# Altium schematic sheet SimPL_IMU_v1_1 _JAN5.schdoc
size 299 x 236 mm
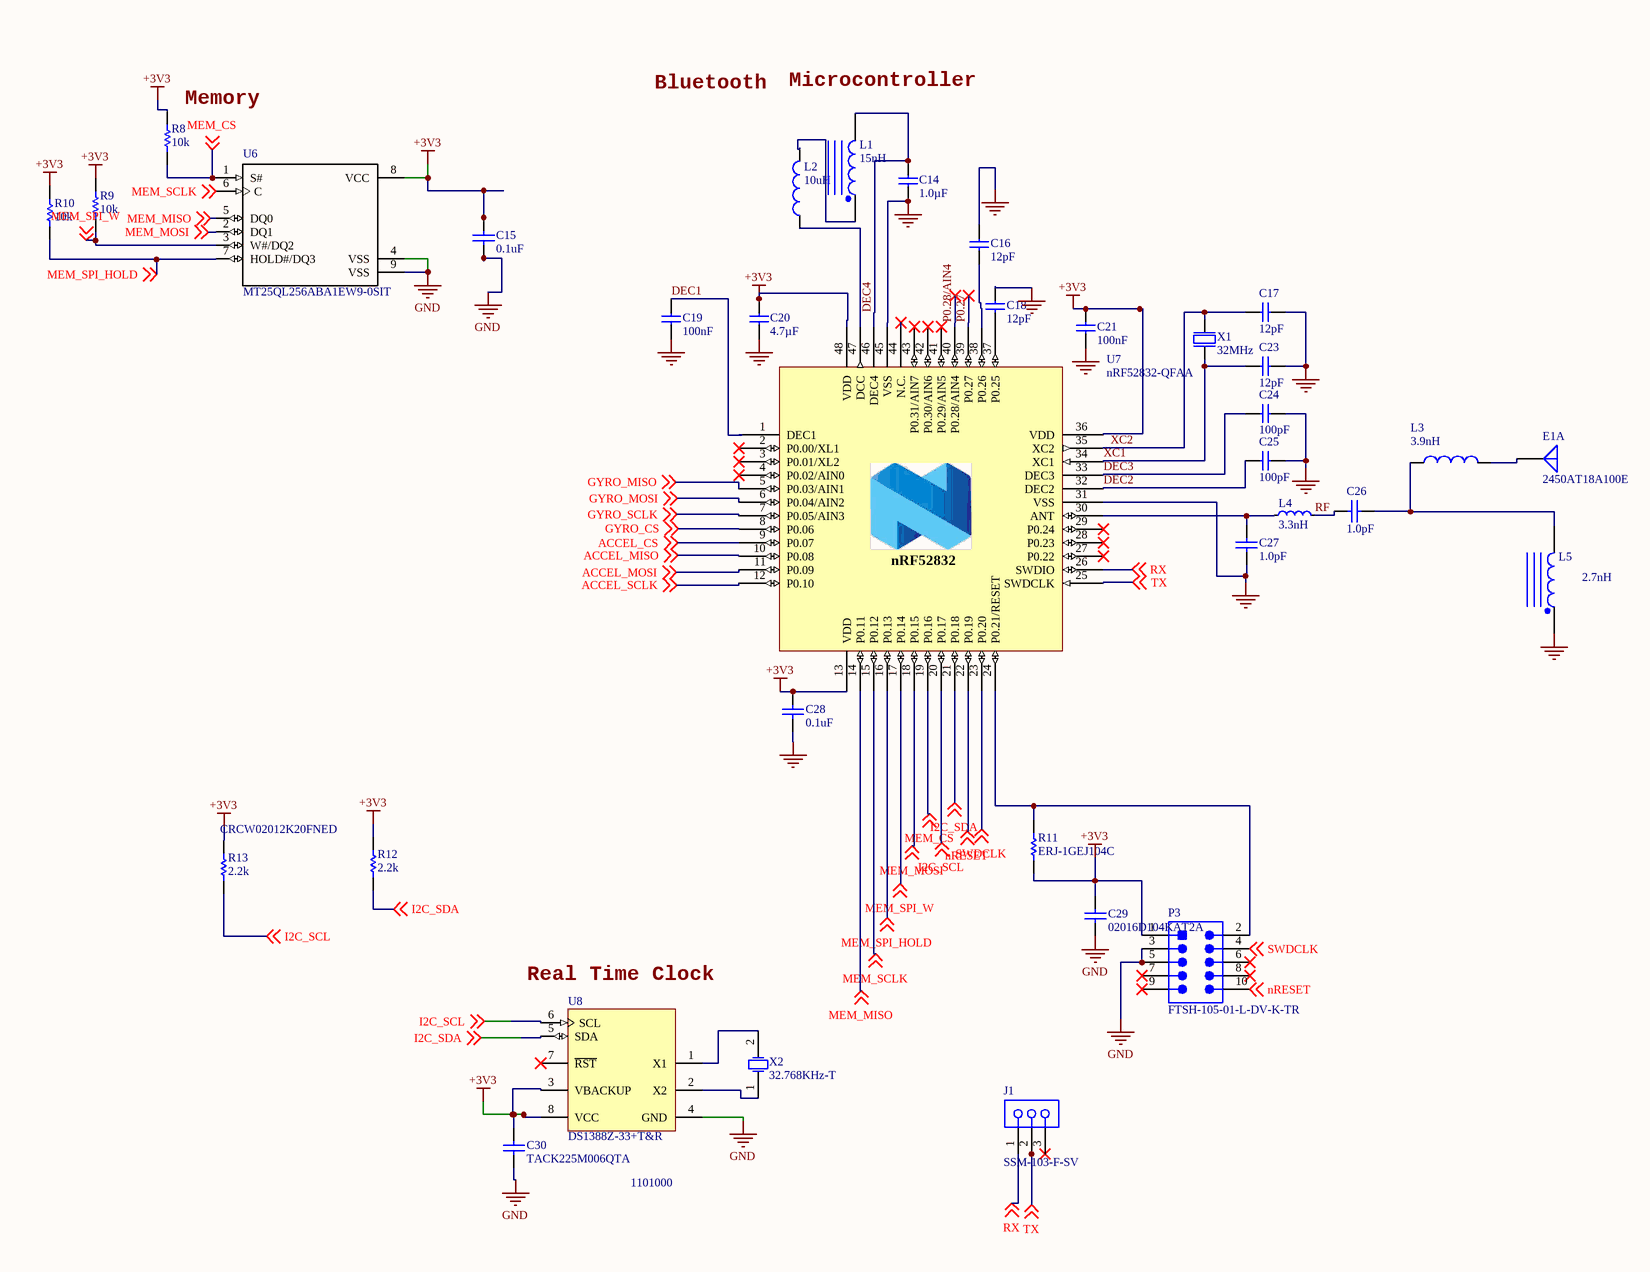
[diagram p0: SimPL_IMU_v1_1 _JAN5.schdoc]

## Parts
C14  1.0µF  [CAPC1005X04L]
C15  0.1uF  [CAPC0603X33X15LL03T05]
C16  12pF  [CAPC0603X03L]
C17  12pF  [CAPC0603X03L]
C18  12pF  [CAPC0603X03L]
C19  100nF  [CAPC0603X03L]
C20  4.7µF  [CAPC1608X06L]
C21  100nF  [CAPC0603X03L]
C23  12pF  [CAPC0603X03L]
C24  100pF  [CAPC0603X03L]
C25  100pF  [CAPC0603X03L]
C26  1.0pF  [CAPC1005X55X25NL05T10]
C27  1.0pF  [CAPC1005X55X25NL05T10]
C28  0.1uF  [CAPC0603X33X15LL03T05]
C29  02016D104KAT2A  [CAPC0603X33X15LL03T05]
C30  TACK225M006QTA  [CAPC1005X70X10NL20T00]
E1  2450AT18A100E  [JT-2450AT18A100-2_V]  (part A of 2)
J1  SSM-103-F-SV  [SMTC-SSM-103-X-SV]
L1  15nH  [INDC1005X55X25ML05T10_A]
L2  10uH  [MURA-IND0805_L]
L3  3.9nH  [*INDC1006X60N]
L4  3.3nH  [INDC0603X03L]
L5  2.7nH  [INDC1005X55X25LL05T10_A]
P3  FTSH-105-01-L-DV-K-TR  [SMTC-FTSH-105-01-L-DV-K_V]
R8  10k  [RESC1005X40X25NL05T05]
R9  10k  [RESC1005X40X25NL05T05]
R10  10k  [RESC1005X40X25NL05T05]
R11  ERJ-1GEJ104C  [RESC0603X26X15LL03T05]
R12  2.2k  [RESC0603X28X15ML05T05]
R13  2.2k  Part Number: CRCW02012K20FNED  [RESC0603X28X15ML05T05]
U6  MT25QL256ABA1EW9-0SIT  [*SON127P600X800X80-9N]
U7  nRF52832-QFAA  [QFN40P600X600X90-48N]
U8  DS1388Z-33+T&R  [S8+4_M]
X1  32MHz  [BT-XTAL_2016]
X2  32.768KHz-T  [ABRA-ABS07-2_V]

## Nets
+3V3: C15.2 C20.1 C21.1 C28.2 C29.2 C30.2 P3.1 R8.2 R9.2 R10.2 R11.1 R12.2 R13.2 U6.8(VCC) U7.13(VDD) U7.36(VDD) U7.48(VDD) U8.3(VBACKUP) U8.8(VCC)
GND: C14.1 C15.1 C16.1 C17.1 C18.1 C19.2 C20.2 C21.2 C23.1 C24.2 C25.1 C27.1 C28.1 C29.1 C30.1 L5.1 P3.3 P3.5 U6.4(VSS) U6.9(VSS) U7.31(VSS) U7.45(VSS) U7.49(GND) U8.4(GND) X1.2(GND) X1.4(GND)
ACCEL_CS: U7.9(P0.07) ; off-sheet ACCEL_CS
ACCEL_MISO: U7.10(P0.08) ; off-sheet ACCEL_MISO
ACCEL_MOSI: U7.11(P0.09) ; off-sheet ACCEL_MOSI
ACCEL_SCLK: U7.12(P0.10) ; off-sheet ACCEL_SCLK
DEC1: C19.1 U7.1(DEC1)
DEC2: C25.2 U7.32(DEC2)
DEC3: C24.1 U7.33(DEC3)
DEC4: C14.2 L1.2 U7.46(DEC4)
GYRO_CS: U7.8(P0.06) ; off-sheet GYRO_CS
GYRO_MISO: U7.5(P0.03/AIN1) ; off-sheet GYRO_MISO
GYRO_MOSI: U7.6(P0.04/AIN2) ; off-sheet GYRO_MOSI
GYRO_SCLK: U7.7(P0.05/AIN3) ; off-sheet GYRO_SCLK
I2C_SCL: R13.1 U7.20(P0.17) U8.6(SCL) ; off-sheet I2C_SCL
I2C_SDA: R12.1 U7.21(P0.18) U8.5(SDA) ; off-sheet I2C_SDA
MEM_CS: R8.1 U6.1(S#) U7.19(P0.16) ; off-sheet MEM_CS
MEM_MISO: U6.5(DQ0) U7.14(P0.11) ; off-sheet MEM_MISO
MEM_MOSI: U6.2(DQ1) U7.18(P0.15) ; off-sheet MEM_MOSI
MEM_SCLK: U6.6(C) U7.15(P0.12) ; off-sheet MEM_SCLK
MEM_SPI_HOLD: R10.1 U6.7(HOLD#/DQ3) U7.16(P0.13) ; off-sheet MEM_SPI_HOLD
MEM_SPI_W: R9.1 U6.3(W#/DQ2) U7.17(P0.14) ; off-sheet MEM_SPI_W
nRESET: P3.10 U7.22(P0.19) ; off-sheet nRESET
P0.27: U7.39(P0.27)
P0.28/AIN4: U7.40(P0.28/AIN4)
RF: C26.2 L4.2
RX: J1.1 U7.26(SWDIO) ; off-sheet RX
SWDCLK: P3.4 U7.23(P0.20) ; off-sheet SWDCLK
TX: J1.2 U7.25(SWDCLK) ; off-sheet TX
XC1: C23.2 U7.34(XC1) X1.1(inp)
XC2: C17.2 U7.35(XC2) X1.3(out)
NetC16_2: C16.2 U7.38(P0.26)
NetC18_2: C18.2 U7.37(P0.25)
NetC26_1: C26.1 L3.1 L5.2
NetC27_2: C27.2 L4.1 U7.30(ANT)
NetE1_1: E1.1(FP) L3.2
NetL1_1: L1.1 L2.2
NetL2_1: L2.1 U7.47(DCC)
NetP3_2: P3.2 R11.2 U7.24(P0.21/RESET)
NetU8_1: U8.1(X1) X2.2(X2)
NetU8_2: U8.2(X2) X2.1(X2)

Not connected (* = marked no-connect by the designer): J1 3*; P3 6* 7* 8* 9*; U7 2(P0.00/XL1)* 3(P0.01/XL2)* 4(P0.02/AIN0)* 27(P0.22)* 28(P0.23)* 29(P0.24)* 41(P0.29/AIN5)* 42(P0.30/AIN6)* 43(P0.31/AIN7)* 44(N.C.)*; U8 7(~{RST})*

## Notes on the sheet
- (near R8) Memory
- Bluetooth
- Microcontroller
- (near U8) Real Time Clock
- 1101000

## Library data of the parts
C14 = C0402-1µ0: Capacitor, X5R, ±5%; Part Number: C0402C105K9PACTU; Note: 6.3V; Artikkelnr Noca: 20039235; Artikkelnr Simpro: N.A.
C15 C28 = CMP-2010-01264-1: Part Number: GRM033R61A104KE15D; Manufacturer: Murata
C16-C18 C23 = C0201-12p: Capacitor, NP0, ±2%; Part Number: CC0201JRNPO8BN120; Note: 50V; Artikkelnr Noca: N.A.
C19 C21 = C0201-100n: Capacitor, X7R, ±10%; Part Number: CC0201KRX5R5BB104; Note: 16V; Artikkelnr Noca: N.A.
C20 = C0603-4µ7: Capacitor, X5R, ±10%; Part Number: C0603C475K9PACTU; Note: 6.3V; Artikkelnr Noca: 20069060; Artikkelnr Simpro: N.A.
C24 C25 = C0201-100p: Capacitor, NP0, ±5%; Part Number: CC0201JRNPO9BN101; Note: Chip Cap 1%; Artikkelnr Noca: N.A.
C26 C27 = CMP-2008-03808-1: Manufacturer: Murata; Part Number: GJM1555C1H1R0BB01D
C29 = CMP-2010-00159-1: Manufacturer: AVX Interconnect / Elco
C30 = CMP-2008-00070-1: Manufacturer: AVX Interconnect / Elco
E1 = CMP-2000-05167-1: Ceramic Antenna, 2.45 GHZ, 2 W, -40 to 125 degC, 2-Pin SMD, RoHS, Tape and Reel; Manufacturer: Johanson Technology; Maximum Frequency: 2500MHz; Typical Antenna Gain: 0.5dB; Minimum Frequency: 2400MHz
J1 = CMP-1023-00202-1: Tiger Claw(TM) Surface Mount Socket, Vertical, -55 to 125 degC, 2.54 mm Pitch, 3-Pin, Female, RoHS; Manufacturer: Samtec; Pitch: 2.54 mm
L1 = CMP-2100-03652-1: Chip Inductor, 15 nH, +/- 5%, 100 MHz, -55 to 125 degC, 0402 (1005 Metric), RoHS, Paper Tape; Manufacturer: Murata; Part Number: HK100515NJ-T; DC Current: 300mA; Q Factor: 8; Self Resonant Frequency: 2.5GHz; DC Resistance (DCR): 320mOhm; Test Frequency: 100MHz; Shielding: Unshielded; Core Material: Air
L2 = CMP-2000-06587-1: Fixed Inductor, 10 uH, +/-20%, -55 to 125 degC, 2-Pin SMD (0805), RoHS, Tape and Reel; Manufacturer: Bourns; Part Number: CV201210-100K; Tolerance (%): 20%; DC Resistance: 0.6; Inductance-Nom: 10H; Rated Current-Max: 100mA
L3 = MHQ1005P3N9CT000: Inductor, 3.9nh, 0.2nh, 0.9a, 0402; Manufacturer Part Number: L-07C3N9SV6T; MF: TDK
L4 = L0201-3n3: High frequency chip inductor ±5%; Part Number: LQP03TN3N3B02D; Manufacturer: Murata; Artikkelnr Noca: N.A.
L5 = CMP-2000-06580-1: Chip Inductor, 2.7 nH, +/- 0.3 nH, 300 mA, -55 to 125 degC, 0402 (1005 Metric), RoHS, Tape and Reel; Manufacturer: Murata; Part Number: L-07C2N7SV6T; Type: Multilayer; Frequency - Self Resonant: 6GHz; Shielding: Unshielded; Online Catalog: LQG15HxSeries; Other Names: 490-2615-2; Catalog Drawings: LQG15HSSeriesTopLQG15HSSeriesEnd; Q @ Freq: 8@100MHz; DC Resistance (DCR): 150mOhmMax; Frequency - Test: 100MHz; Product Training Modules: InductorProducts; Current Rating: 300mA; Material - Core: Air; Tolerance: ±0.3nH
P3 = CMP-2000-06293-1: Male Header, Pitch 1.27 mm, 2 x 5 Position, Height 6.12 mm, -55 to 125 degC, RoHS, Tape and Reel; Manufacturer: Amphenol; Part Number: 20021121-00010C4LF; Pitch: 1.27mm; Rad Hard: No; Gender: HDR; Number of Contacts: 10
R8-R10 = CMP-2002-00607-3: Chip Resistor, 10 KOhm, +/- 1%, 100 mW, -55 to 155 degC, 0402 (1005 Metric), RoHS, Tape and Reel; Manufacturer: Basic Passives; PartNumber: ERJ-2RKF1002X; Case\/Package: 0402; Resistance: 10 KOhm; Voltage Rating: 50 V; Power Rating: 100 mW
R11 = CMP-2004-03147-1: Manufacturer: Panasonic
R12 = CMP-2004-00412-1: Manufacturer: Vishay Dale; Part Number: CRCW02012K20FNED
R13 = CMP-2004-00412-1: Manufacturer: Vishay Dale
U6 = MT25QL256ABA1EW9-0SIT: NOR Flash Serial-SPI 3.3V 256Mbit 256M x 1bit 8-Pin WPDFN; MF: Micron Technology
U7 = nRF52832_QFAA: Multi-protocol Bluetooth Low Energy, ANT and 2.4GHz proprietary system-on-chip; Manufacturer: Nordic Semiconductor; Artikkelnr Noca: N.A.
U8 = CMP-0254-00385-1: I2C Real-Time Clock/Supervisor with Trickle Charger and 512 Byte EEPROM, 3.3V, 8-Pin SO, -40 to 85 degC, Pb-Free, Reel
X1 = XTAL_SMD2016_32MHz_8pF_Epson: XTAL SMD 2016, 32MHz, Cl=8pF, Total Tol: ±40ppm; Manufacturer: ECS Inc.; Manufacturer Part Number: ECS-320-8-37B-CKY-TR; Note: XTAL SMD 32.000MHz; Artikkelnr Noca: N.A.
X2 = CMP-0447-00001-2: Crystal, 32.768 kHz, 12.5 pF, -40 to 85 degC, SMD Low Profile 3.2 x 1.5 x 0.9 mm, Tape and Reel; Manufacturer: Abracon; PartNumber: ABS07-32.768KHz-T; Q Value (Type): 30000; Operation Mode: Flexural Mode (Tuning Fork); Shunt Capacitance (C0): 0.9 to 1.2 pF; Load Capacitance (CL): 12.5 pF; Frequency Tolerance @+25degC: +/- 20 ppm; Drive Level (Type): 0.1 uW; Equivalent Series Resistance (R1): 70 Kohm; Insulation Resistance (Min): 500 Mohm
